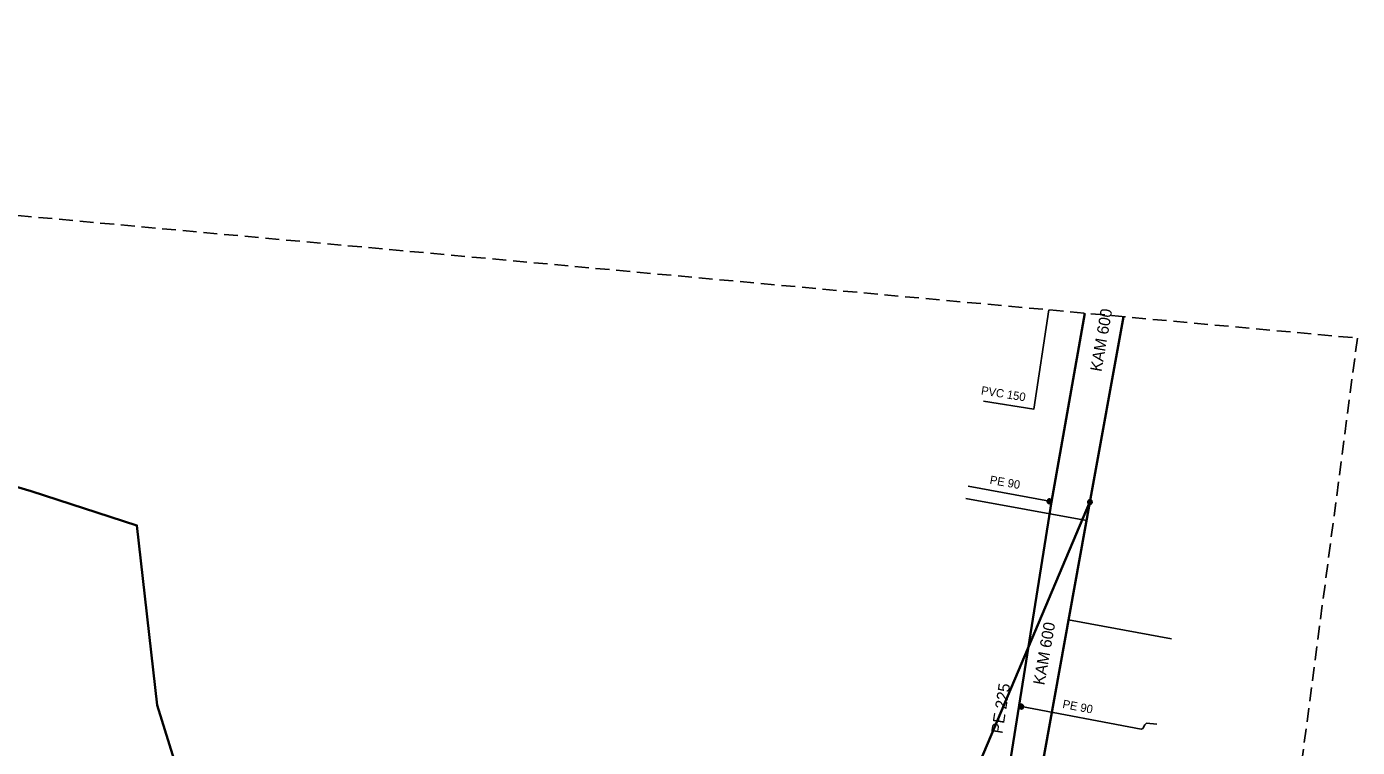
# Model space of a CAD drawing. Extents: x -867121 to -866743, y -1014362 to -1014088.
# Drawn here: x -866869.9 to -866742.8, y -1014157.2 to -1014088.3 of the extents above; entities that cross this region are included whole.
import ezdxf

# ---------------------------------------------------------------- set-up
doc = ezdxf.new("R2010")
doc.units = 0
doc.header["$LTSCALE"] = 0.44
doc.linetypes.add('MEDIUM_DASHED', pattern=[4.5, 3, -1.5])
for name, color, linetype, lineweight in [('1', 7, 'Continuous', 35), ('12', 7, 'Continuous', 13), ('21', 7, 'Continuous', 35), ('23', 7, 'Continuous', 25), ('3', 7, 'Continuous', 25), ('32', 7, 'Continuous', 13), ('62', 7, 'MEDIUM_DASHED', 25)]:
    doc.layers.add(name, color=color, linetype=linetype, lineweight=lineweight)

msp = doc.modelspace()

# ---------------------------------------------------------------- linework, layer by layer
at = {"layer": '1'}
for points in [[(-866791.979, -1014256.58), (-866792.57, -1014256.02), (-866792.709, -1014255.69), (-866792.69, -1014255.37), (-866792.5, -1014254.9), (-866792.3, -1014254.24), (-866792, -1014252.89), (-866783.03, -1014202.67), (-866778.1, -1014171.95), (-866772.02, -1014133.72), (-866768.851, -1014115.7)], [(-866792.574, -1014256.008), (-866841.087, -1014205.753), (-866857.467, -1014153.141), (-866859.393, -1014135.973), (-866869.502, -1014132.716), (-866897.758, -1014124.346), (-866897.929, -1014124.295)]]:
    msp.add_lwpolyline(points, dxfattribs=at)
at = {"layer": '12'}
for points in [[(-866771.995, -1014133.669), (-866772.002, -1014133.617), (-866772.019, -1014133.567), (-866772.048, -1014133.523), (-866772.085, -1014133.486), (-866772.13, -1014133.459), (-866772.179, -1014133.442), (-866772.233, -1014133.438), (-866772.284, -1014133.445), (-866772.333, -1014133.464), (-866772.377, -1014133.493), (-866772.413, -1014133.532), (-866772.439, -1014133.577), (-866772.455, -1014133.628), (-866772.458, -1014133.68), (-866772.45, -1014133.732), (-866772.429, -1014133.781), (-866772.399, -1014133.824), (-866772.36, -1014133.858), (-866772.314, -1014133.884), (-866772.262, -1014133.898), (-866772.21, -1014133.9), (-866772.159, -1014133.89), (-866772.11, -1014133.869), (-866772.068, -1014133.838), (-866772.034, -1014133.797), (-866772.01, -1014133.751), (-866771.997, -1014133.7)], [(-866772.026, -1014133.669), (-866772.032, -1014133.62), (-866772.049, -1014133.574), (-866772.076, -1014133.534), (-866772.114, -1014133.502), (-866772.157, -1014133.48), (-866772.206, -1014133.469), (-866772.255, -1014133.469), (-866772.301, -1014133.482), (-866772.345, -1014133.506), (-866772.38, -1014133.539), (-866772.407, -1014133.58), (-866772.424, -1014133.627), (-866772.428, -1014133.676), (-866772.421, -1014133.724), (-866772.402, -1014133.769), (-866772.372, -1014133.809), (-866772.333, -1014133.84), (-866772.289, -1014133.86), (-866772.242, -1014133.87), (-866772.193, -1014133.868), (-866772.146, -1014133.853), (-866772.103, -1014133.828), (-866772.068, -1014133.794), (-866772.043, -1014133.752), (-866772.029, -1014133.705)], [(-866772.056, -1014133.669), (-866772.061, -1014133.624), (-866772.078, -1014133.582), (-866772.107, -1014133.547), (-866772.142, -1014133.52), (-866772.184, -1014133.503), (-866772.23, -1014133.498), (-866772.274, -1014133.504), (-866772.316, -1014133.523), (-866772.35, -1014133.551), (-866772.377, -1014133.588), (-866772.394, -1014133.63), (-866772.397, -1014133.675), (-866772.391, -1014133.72), (-866772.372, -1014133.761), (-866772.343, -1014133.795), (-866772.306, -1014133.821), (-866772.262, -1014133.837), (-866772.218, -1014133.84), (-866772.173, -1014133.832), (-866772.132, -1014133.812), (-866772.098, -1014133.783), (-866772.073, -1014133.745), (-866772.059, -1014133.702)], [(-866772.086, -1014133.669), (-866772.09, -1014133.628), (-866772.108, -1014133.591), (-866772.136, -1014133.56), (-866772.171, -1014133.539), (-866772.211, -1014133.528), (-866772.252, -1014133.53), (-866772.291, -1014133.543), (-866772.325, -1014133.567), (-866772.35, -1014133.599), (-866772.365, -1014133.637), (-866772.367, -1014133.678), (-866772.36, -1014133.718), (-866772.34, -1014133.754), (-866772.311, -1014133.783), (-866772.274, -1014133.802), (-866772.233, -1014133.81), (-866772.193, -1014133.806), (-866772.154, -1014133.791), (-866772.122, -1014133.765), (-866772.1, -1014133.731), (-866772.087, -1014133.692)], [(-866772.115, -1014133.669), (-866772.12, -1014133.633), (-866772.139, -1014133.601), (-866772.164, -1014133.576), (-866772.198, -1014133.561), (-866772.235, -1014133.558), (-866772.269, -1014133.566), (-866772.301, -1014133.586), (-866772.323, -1014133.614), (-866772.337, -1014133.648), (-866772.337, -1014133.685), (-866772.326, -1014133.72), (-866772.304, -1014133.749), (-866772.274, -1014133.77), (-866772.24, -1014133.78), (-866772.203, -1014133.778), (-866772.169, -1014133.764), (-866772.142, -1014133.741), (-866772.122, -1014133.709), (-866772.115, -1014133.674)], [(-866772.146, -1014133.669), (-866772.151, -1014133.638), (-866772.168, -1014133.612), (-866772.193, -1014133.595), (-866772.223, -1014133.588), (-866772.255, -1014133.592), (-866772.282, -1014133.609), (-866772.299, -1014133.633), (-866772.308, -1014133.664), (-866772.304, -1014133.694), (-866772.289, -1014133.722), (-866772.264, -1014133.741), (-866772.235, -1014133.75), (-866772.203, -1014133.747), (-866772.176, -1014133.733), (-866772.156, -1014133.709), (-866772.146, -1014133.68)], [(-866772.176, -1014133.669), (-866772.181, -1014133.645), (-866772.198, -1014133.627), (-866772.22, -1014133.618), (-866772.245, -1014133.621), (-866772.266, -1014133.635), (-866772.277, -1014133.657), (-866772.277, -1014133.682), (-866772.264, -1014133.703), (-866772.245, -1014133.717), (-866772.22, -1014133.72), (-866772.196, -1014133.711), (-866772.181, -1014133.693)], [(-866772.206, -1014133.669), (-866772.211, -1014133.654), (-866772.225, -1014133.648), (-866772.24, -1014133.652), (-866772.247, -1014133.666), (-866772.244, -1014133.681), (-866772.23, -1014133.69), (-866772.215, -1014133.687), (-866772.206, -1014133.675)], [(-866774.666, -1014153.279), (-866774.672, -1014153.227), (-866774.689, -1014153.177), (-866774.718, -1014153.133), (-866774.755, -1014153.096), (-866774.8, -1014153.069), (-866774.85, -1014153.052), (-866774.903, -1014153.048), (-866774.955, -1014153.055), (-866775.004, -1014153.074), (-866775.047, -1014153.103), (-866775.083, -1014153.142), (-866775.109, -1014153.187), (-866775.125, -1014153.238), (-866775.128, -1014153.29), (-866775.12, -1014153.342), (-866775.1, -1014153.391), (-866775.069, -1014153.434), (-866775.03, -1014153.468), (-866774.984, -1014153.494), (-866774.933, -1014153.508), (-866774.88, -1014153.51), (-866774.829, -1014153.5), (-866774.781, -1014153.479), (-866774.738, -1014153.448), (-866774.704, -1014153.407), (-866774.68, -1014153.361), (-866774.668, -1014153.31)], [(-866774.696, -1014153.279), (-866774.702, -1014153.23), (-866774.719, -1014153.184), (-866774.747, -1014153.144), (-866774.784, -1014153.112), (-866774.828, -1014153.09), (-866774.876, -1014153.079), (-866774.925, -1014153.079), (-866774.972, -1014153.092), (-866775.015, -1014153.116), (-866775.051, -1014153.149), (-866775.078, -1014153.19), (-866775.094, -1014153.237), (-866775.098, -1014153.286), (-866775.091, -1014153.334), (-866775.072, -1014153.379), (-866775.042, -1014153.419), (-866775.004, -1014153.45), (-866774.96, -1014153.47), (-866774.912, -1014153.48), (-866774.863, -1014153.478), (-866774.816, -1014153.463), (-866774.773, -1014153.438), (-866774.739, -1014153.404), (-866774.713, -1014153.362), (-866774.699, -1014153.315)], [(-866774.726, -1014153.279), (-866774.732, -1014153.234), (-866774.749, -1014153.192), (-866774.777, -1014153.157), (-866774.813, -1014153.13), (-866774.855, -1014153.113), (-866774.9, -1014153.108), (-866774.945, -1014153.114), (-866774.986, -1014153.133), (-866775.021, -1014153.161), (-866775.048, -1014153.198), (-866775.064, -1014153.24), (-866775.068, -1014153.285), (-866775.061, -1014153.33), (-866775.042, -1014153.371), (-866775.013, -1014153.405), (-866774.976, -1014153.431), (-866774.933, -1014153.447), (-866774.888, -1014153.45), (-866774.843, -1014153.442), (-866774.803, -1014153.422), (-866774.769, -1014153.393), (-866774.743, -1014153.355), (-866774.729, -1014153.312)], [(-866774.756, -1014153.279), (-866774.761, -1014153.238), (-866774.779, -1014153.201), (-866774.806, -1014153.17), (-866774.841, -1014153.149), (-866774.881, -1014153.138), (-866774.922, -1014153.14), (-866774.961, -1014153.153), (-866774.995, -1014153.177), (-866775.02, -1014153.209), (-866775.035, -1014153.247), (-866775.038, -1014153.288), (-866775.03, -1014153.328), (-866775.01, -1014153.364), (-866774.981, -1014153.393), (-866774.944, -1014153.412), (-866774.904, -1014153.42), (-866774.863, -1014153.416), (-866774.825, -1014153.401), (-866774.793, -1014153.375), (-866774.77, -1014153.341), (-866774.757, -1014153.302)], [(-866774.786, -1014153.279), (-866774.791, -1014153.243), (-866774.809, -1014153.211), (-866774.835, -1014153.186), (-866774.869, -1014153.171), (-866774.905, -1014153.168), (-866774.94, -1014153.176), (-866774.971, -1014153.196), (-866774.994, -1014153.224), (-866775.007, -1014153.258), (-866775.007, -1014153.295), (-866774.996, -1014153.33), (-866774.975, -1014153.359), (-866774.945, -1014153.38), (-866774.91, -1014153.39), (-866774.873, -1014153.388), (-866774.839, -1014153.374), (-866774.812, -1014153.351), (-866774.793, -1014153.319), (-866774.786, -1014153.284)], [(-866774.816, -1014153.279), (-866774.821, -1014153.248), (-866774.838, -1014153.222), (-866774.864, -1014153.205), (-866774.894, -1014153.198), (-866774.925, -1014153.202), (-866774.952, -1014153.219), (-866774.97, -1014153.243), (-866774.978, -1014153.274), (-866774.974, -1014153.304), (-866774.959, -1014153.332), (-866774.934, -1014153.351), (-866774.905, -1014153.36), (-866774.874, -1014153.357), (-866774.846, -1014153.343), (-866774.826, -1014153.319), (-866774.816, -1014153.29)], [(-866774.846, -1014153.279), (-866774.851, -1014153.255), (-866774.868, -1014153.237), (-866774.891, -1014153.228), (-866774.915, -1014153.231), (-866774.936, -1014153.245), (-866774.947, -1014153.267), (-866774.947, -1014153.292), (-866774.934, -1014153.313), (-866774.915, -1014153.327), (-866774.89, -1014153.33), (-866774.867, -1014153.321), (-866774.851, -1014153.303)], [(-866774.876, -1014153.279), (-866774.881, -1014153.264), (-866774.896, -1014153.258), (-866774.911, -1014153.262), (-866774.918, -1014153.276), (-866774.914, -1014153.291), (-866774.901, -1014153.3), (-866774.886, -1014153.297), (-866774.876, -1014153.285)]]:
    msp.add_lwpolyline(points, close=True, dxfattribs=at)
at = {"layer": '21'}
for p, q in [((-866768.346, -1014133.738), (-866765.128, -1014116.041)), ((-866773.421, -1014161.649), (-866768.346, -1014133.738))]:
    msp.add_line(p, q, dxfattribs=at)
msp.add_lwpolyline([(-866867.906, -1014313.414), (-866804.195, -1014269.207), (-866794.318, -1014228.125), (-866791.378, -1014202.173), (-866784.04, -1014170.77), (-866768.345, -1014133.735)], dxfattribs=at)
at = {"layer": '23'}
for p, q in [((-866780.215, -1014133.412), (-866768.668, -1014135.512)), ((-866760.552, -1014146.792), (-866770.394, -1014145.002))]:
    msp.add_line(p, q, dxfattribs=at)
msp.add_lwpolyline([(-866778.527, -1014124.104), (-866773.713, -1014124.872), (-866772.267, -1014115.388)], dxfattribs=at)
at = {"layer": '3'}
for points in [[(-866772.02, -1014133.72), (-866772.22, -1014133.66), (-866779.994, -1014132.233)], [(-866775.13, -1014153.25), (-866774.89, -1014153.27), (-866763.44, -1014155.44), (-866763.3, -1014155.36), (-866763.109, -1014155), (-866762.959, -1014154.86), (-866761.96, -1014154.96)]]:
    msp.add_lwpolyline(points, dxfattribs=at)
at = {"layer": '32'}
for points in [[(-866768.115, -1014133.738), (-866768.121, -1014133.686), (-866768.138, -1014133.636), (-866768.167, -1014133.592), (-866768.204, -1014133.555), (-866768.249, -1014133.528), (-866768.299, -1014133.511), (-866768.352, -1014133.507), (-866768.404, -1014133.514), (-866768.453, -1014133.533), (-866768.496, -1014133.562), (-866768.532, -1014133.601), (-866768.558, -1014133.646), (-866768.574, -1014133.697), (-866768.577, -1014133.749), (-866768.569, -1014133.801), (-866768.549, -1014133.85), (-866768.518, -1014133.893), (-866768.479, -1014133.927), (-866768.433, -1014133.953), (-866768.382, -1014133.967), (-866768.329, -1014133.969), (-866768.278, -1014133.959), (-866768.23, -1014133.938), (-866768.187, -1014133.907), (-866768.153, -1014133.866), (-866768.129, -1014133.82), (-866768.117, -1014133.769)], [(-866768.145, -1014133.738), (-866768.151, -1014133.689), (-866768.168, -1014133.643), (-866768.196, -1014133.603), (-866768.233, -1014133.571), (-866768.277, -1014133.549), (-866768.325, -1014133.538), (-866768.374, -1014133.538), (-866768.421, -1014133.551), (-866768.464, -1014133.575), (-866768.5, -1014133.608), (-866768.527, -1014133.649), (-866768.543, -1014133.696), (-866768.547, -1014133.745), (-866768.54, -1014133.793), (-866768.521, -1014133.838), (-866768.491, -1014133.878), (-866768.453, -1014133.909), (-866768.409, -1014133.929), (-866768.361, -1014133.939), (-866768.312, -1014133.937), (-866768.265, -1014133.922), (-866768.222, -1014133.897), (-866768.188, -1014133.863), (-866768.162, -1014133.821), (-866768.148, -1014133.774)], [(-866768.175, -1014133.738), (-866768.181, -1014133.693), (-866768.198, -1014133.651), (-866768.226, -1014133.616), (-866768.262, -1014133.589), (-866768.304, -1014133.572), (-866768.349, -1014133.567), (-866768.394, -1014133.573), (-866768.435, -1014133.592), (-866768.47, -1014133.62), (-866768.497, -1014133.657), (-866768.513, -1014133.699), (-866768.517, -1014133.744), (-866768.51, -1014133.789), (-866768.491, -1014133.83), (-866768.462, -1014133.864), (-866768.425, -1014133.89), (-866768.382, -1014133.906), (-866768.337, -1014133.909), (-866768.292, -1014133.901), (-866768.252, -1014133.881), (-866768.218, -1014133.852), (-866768.192, -1014133.814), (-866768.178, -1014133.771)], [(-866768.205, -1014133.738), (-866768.21, -1014133.697), (-866768.228, -1014133.66), (-866768.255, -1014133.629), (-866768.29, -1014133.608), (-866768.33, -1014133.597), (-866768.371, -1014133.599), (-866768.41, -1014133.612), (-866768.444, -1014133.636), (-866768.469, -1014133.668), (-866768.484, -1014133.706), (-866768.487, -1014133.747), (-866768.479, -1014133.787), (-866768.459, -1014133.823), (-866768.43, -1014133.852), (-866768.393, -1014133.871), (-866768.353, -1014133.879), (-866768.312, -1014133.875), (-866768.274, -1014133.86), (-866768.242, -1014133.834), (-866768.219, -1014133.8), (-866768.206, -1014133.761)], [(-866768.235, -1014133.738), (-866768.24, -1014133.702), (-866768.258, -1014133.67), (-866768.284, -1014133.645), (-866768.318, -1014133.63), (-866768.354, -1014133.627), (-866768.389, -1014133.635), (-866768.42, -1014133.655), (-866768.443, -1014133.683), (-866768.456, -1014133.717), (-866768.456, -1014133.754), (-866768.445, -1014133.789), (-866768.424, -1014133.818), (-866768.394, -1014133.839), (-866768.359, -1014133.849), (-866768.322, -1014133.847), (-866768.288, -1014133.833), (-866768.261, -1014133.81), (-866768.242, -1014133.778), (-866768.235, -1014133.743)], [(-866768.265, -1014133.738), (-866768.27, -1014133.707), (-866768.287, -1014133.681), (-866768.313, -1014133.664), (-866768.343, -1014133.657), (-866768.374, -1014133.661), (-866768.401, -1014133.678), (-866768.419, -1014133.702), (-866768.427, -1014133.733), (-866768.423, -1014133.763), (-866768.408, -1014133.791), (-866768.384, -1014133.81), (-866768.354, -1014133.819), (-866768.323, -1014133.816), (-866768.295, -1014133.802), (-866768.275, -1014133.778), (-866768.265, -1014133.749)], [(-866768.295, -1014133.738), (-866768.3, -1014133.714), (-866768.317, -1014133.696), (-866768.34, -1014133.687), (-866768.364, -1014133.69), (-866768.385, -1014133.704), (-866768.396, -1014133.726), (-866768.396, -1014133.751), (-866768.384, -1014133.772), (-866768.364, -1014133.786), (-866768.339, -1014133.789), (-866768.316, -1014133.78), (-866768.3, -1014133.762)], [(-866768.325, -1014133.738), (-866768.33, -1014133.723), (-866768.345, -1014133.717), (-866768.36, -1014133.721), (-866768.367, -1014133.735), (-866768.363, -1014133.75), (-866768.35, -1014133.759), (-866768.335, -1014133.756), (-866768.325, -1014133.744)]]:
    msp.add_lwpolyline(points, close=True, dxfattribs=at)
at = {"layer": '62'}
msp.add_lwpolyline([(-867067.961, -1014088.34), (-866742.796, -1014118.083), (-866768.922, -1014317.041), (-866980.741, -1014362.46), (-867121.419, -1014295.739)], close=True, dxfattribs=at)

# ---------------------------------------------------------------- texts
at = {"layer": '1'}
for s, height, rotation, p in [('KAM 600 ', 1.1, 80, (-866767.256, -1014121.342)), ('PVC 150 ', 0.8, 351, (-866778.791, -1014123.455)), ('PE 90 ', 0.8, 350, (-866777.965, -1014131.994)), ('KAM 600 ', 1.1, 80, (-866772.703, -1014151.275)), ('PE 225', 1.1, 81, (-866776.713, -1014155.912)), ('PE 90 ', 0.8, 349, (-866771.017, -1014153.392))]:
    msp.add_text(s, height=height, rotation=rotation, dxfattribs=at).set_placement(p)

doc.saveas('drawing.dxf')
